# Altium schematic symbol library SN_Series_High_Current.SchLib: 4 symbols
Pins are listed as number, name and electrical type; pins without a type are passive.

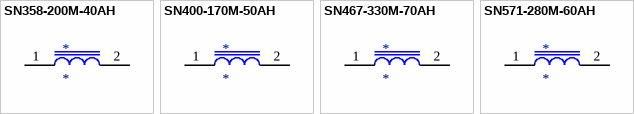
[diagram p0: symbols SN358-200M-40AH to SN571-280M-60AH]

## SN358-200M-40AH
designator *
POWER INDUCTOR 40 A, 20 uH, 3.5 mOhms, OD 46 mm, HT 21 mm; Manufacturer #1: CWS; Current: 40 A; Inductance: 20 uH; OD: 46 mm
footprint SN358-200M-40AH
pins: 1, 2

## SN400-170M-50AH
designator *
POWER INDUCTOR 50 A, 17 uH, 3 mOhms, OD 47 mm, HT 25.4 mm; Manufacturer #1: CWS; Current: 50 A; DCR: 3 mOhms; Inductance: 17 uH; OD: 47 mm
footprint SN400-170M-50AH
pins: 1, 2

## SN467-330M-70AH
designator *
POWER INDUCTOR 70 A, 33 uH, 2.5 mOhms, OD 56 mm, HT 30 mm; Manufacturer #1: CWS; Current: 70 A; Inductance: 33 uH; OD: 56 mm
footprint SN467-330M-70AH
pins: 1, 2

## SN571-280M-60AH
designator *
POWER INDUCTOR 60 A, 28 uH, 3 mOhms, OD 66 mm, HT 27 mm; Manufacturer #1: CWS; Current: 60 A; DCR: 3 mOhms; Inductance: 28 uH; OD: 66 mm
footprint SN571-280M-60AH
pins: 1, 2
